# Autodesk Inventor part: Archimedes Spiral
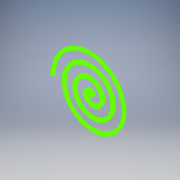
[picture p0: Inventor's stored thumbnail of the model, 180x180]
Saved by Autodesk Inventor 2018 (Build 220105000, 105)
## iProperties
Created: 2008-02
Part Number: Archimedes Spiral
Document SubType Name: Modeling
Designer: Autodesk, Inc.
Density: 1 g/cm^3
Material: Generic
Appearance: Default
Author: Autodesk, Inc.
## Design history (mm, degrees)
sketch "Sketch1"
  geometry: 300 further points
  constraints: 300 other
